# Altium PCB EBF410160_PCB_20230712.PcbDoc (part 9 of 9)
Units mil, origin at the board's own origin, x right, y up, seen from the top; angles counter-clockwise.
Board outline 5393.69 x 3858.26 mil, 6 copper layers (TOP, GND02, ART03, POW04, GND05, BOTTOM), stack 47.2 mil thick; 572 components, 434 nets, 2057 pads, 1177 vias.
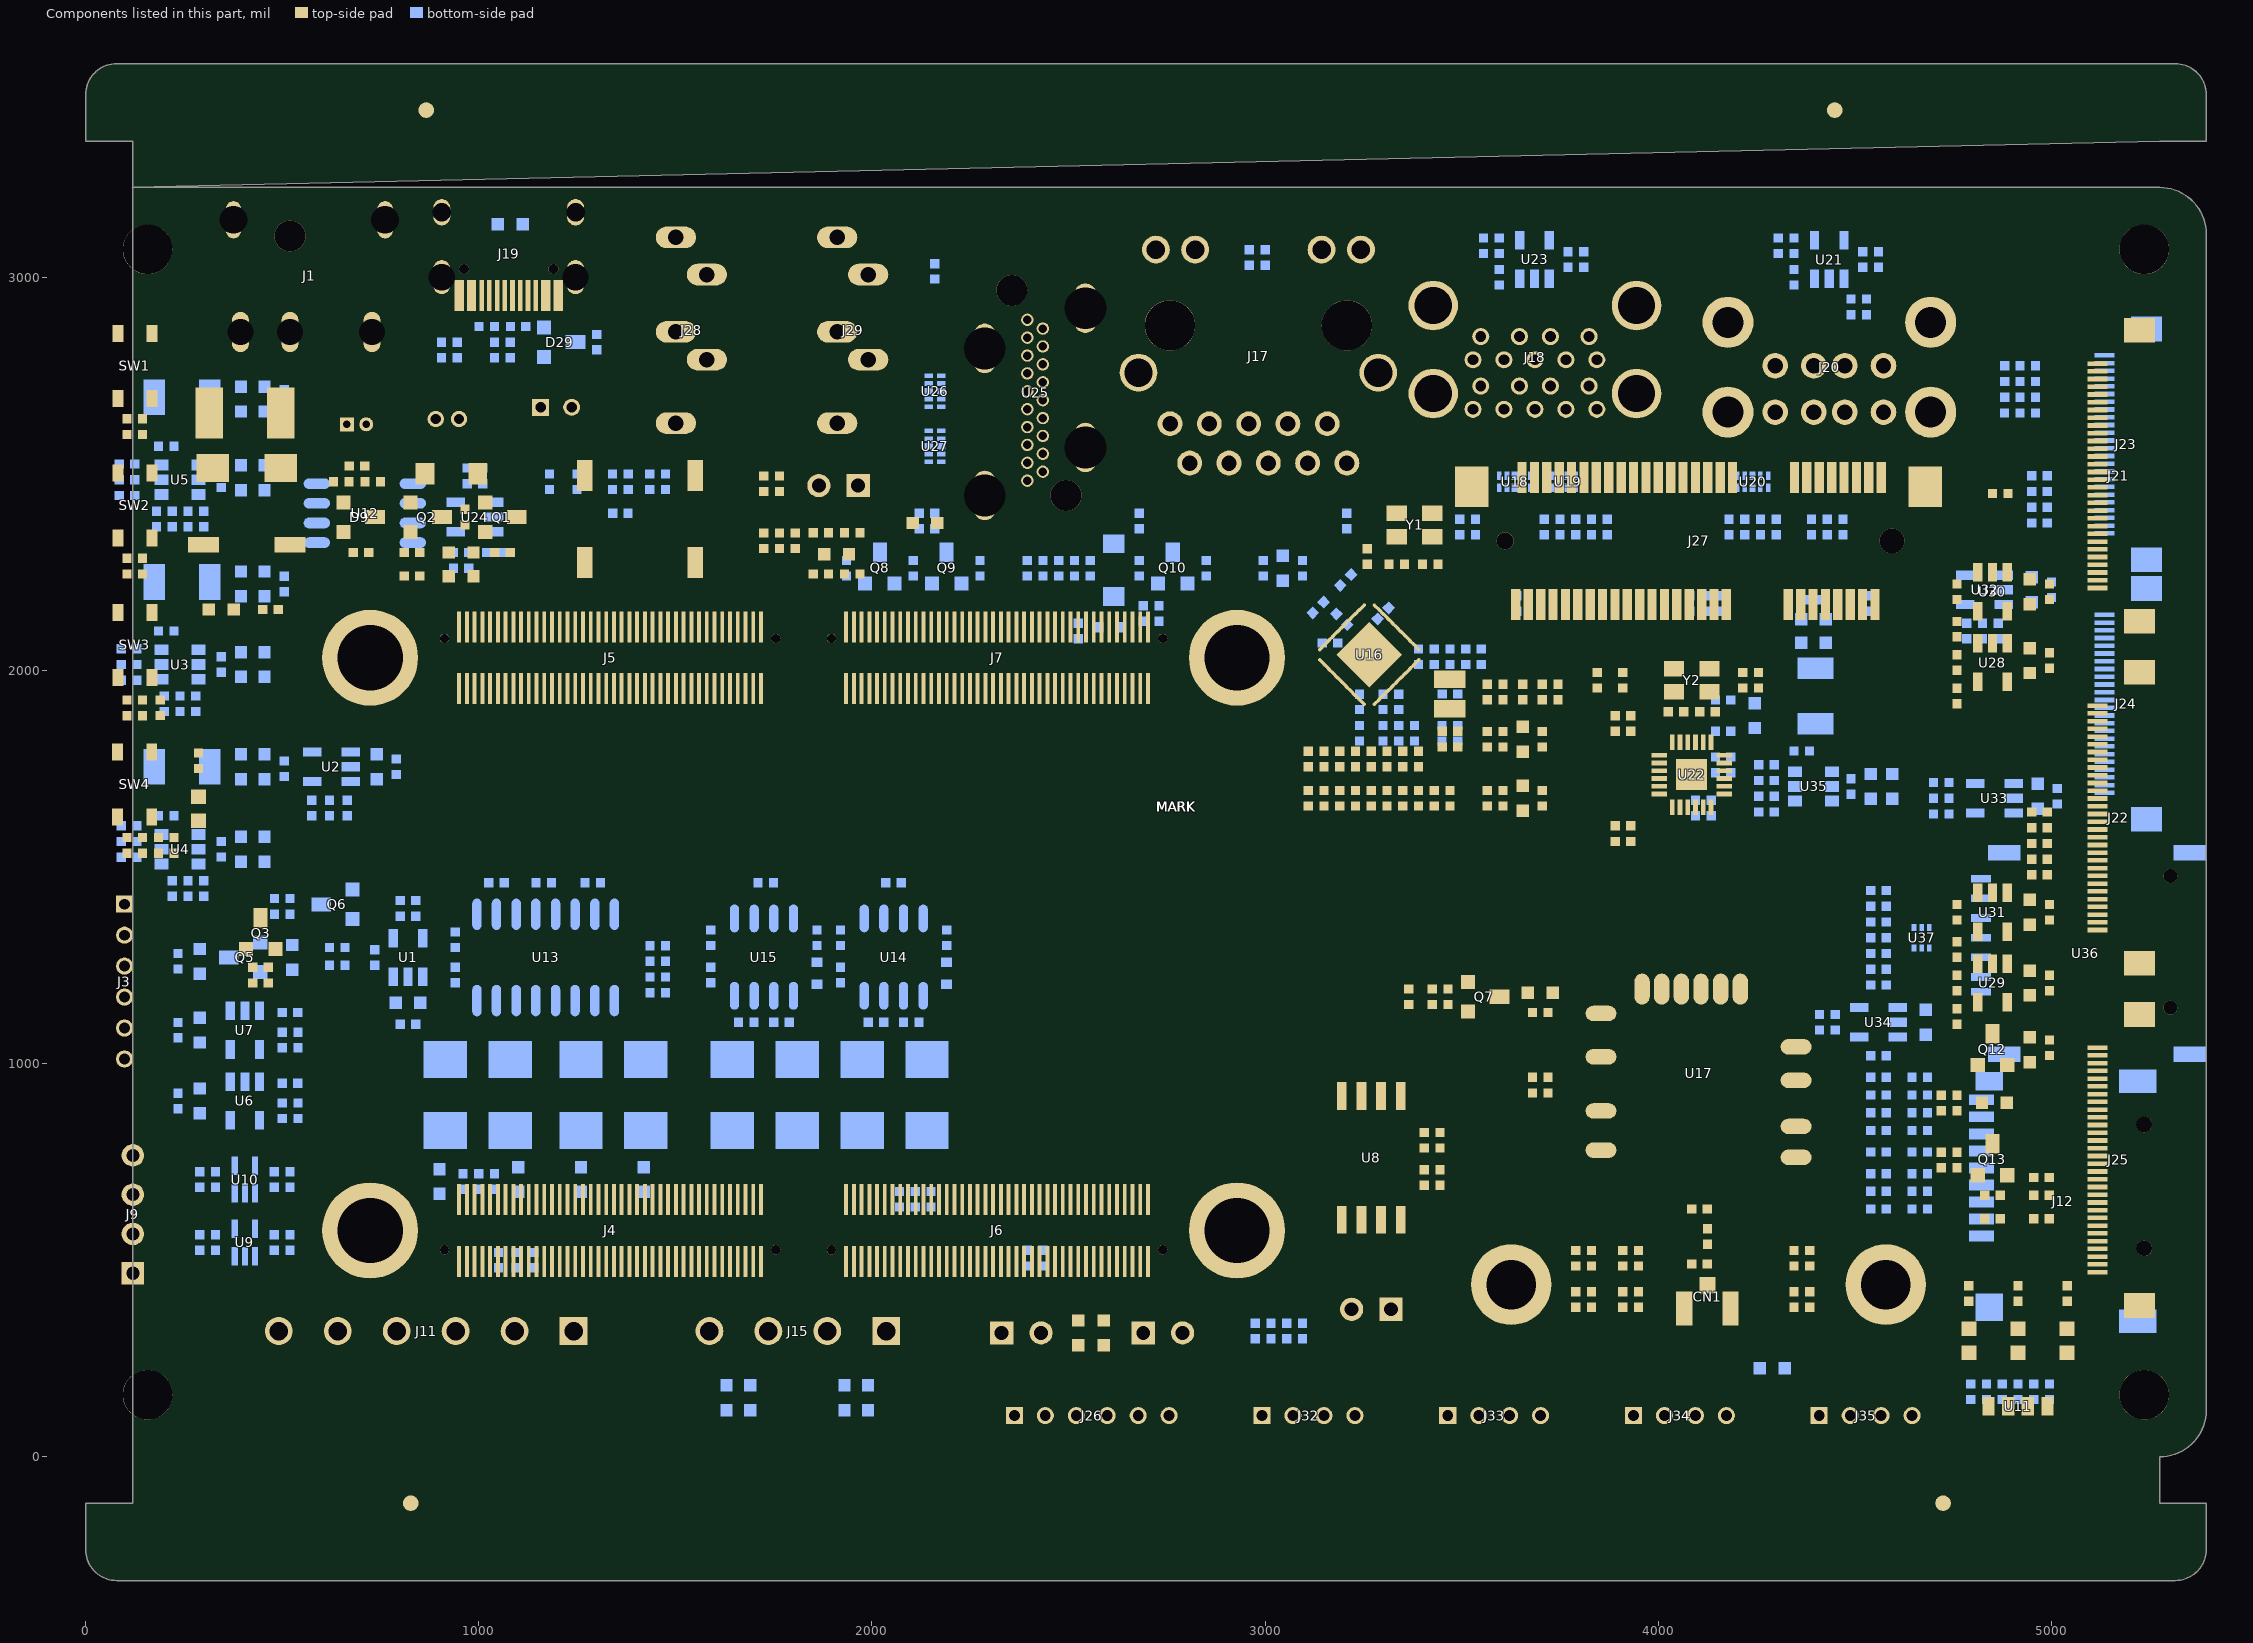
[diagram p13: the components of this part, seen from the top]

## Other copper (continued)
BOTTOM:
  region net HDMI_TX0N_PORT: 2379.42,2723.28 2379.42,2709.97 2395.6,2709.54 2395.17,2725.72 2381.86,2725.72 2381.65,2725.71 2381.44,2725.68 2381.23,2725.63 2381.03,2725.57 2380.83,2725.49 2380.64,2725.39 2380.46,2725.28 2380.29,2725.15 2380.14,2725 2379.99,2724.85 2379.86,2724.68 2379.75,2724.5 2379.65,2724.31 2379.57,2724.11 2379.51,2723.91 2379.46,2723.7 2379.43,2723.49 2379.42,2723.28
  region net HDMI_TXCLKN_PORT: 2413.99,2640.17 2423.41,2630.76 2435.15,2641.9 2423.41,2653.03 2413.99,2643.62 2413.85,2643.47 2413.72,2643.3 2413.61,2643.12 2413.51,2642.93 2413.43,2642.73 2413.36,2642.53 2413.32,2642.32 2413.29,2642.11 2413.28,2641.9 2413.29,2641.69 2413.32,2641.47 2413.36,2641.27 2413.43,2641.06 2413.51,2640.87 2413.61,2640.68 2413.72,2640.5 2413.85,2640.33 2413.99,2640.17
  region net SS_TXN: 3793.25,2792.32 3780.33,2805.24 3764.24,2790.12 3780.33,2775 3793.25,2787.92 3793.43,2788.12 3793.6,2788.33 3793.74,2788.56 3793.87,2788.8 3793.97,2789.05 3794.06,2789.31 3794.11,2789.58 3794.15,2789.85 3794.16,2790.12 3794.15,2790.39 3794.11,2790.66 3794.06,2790.93 3793.97,2791.18 3793.87,2791.44 3793.74,2791.68 3793.6,2791.91 3793.43,2792.12 3793.25,2792.32
  region net HDMI_TXDDC_SCL_PORT: 2375.08,2571.36 2384.03,2562.41 2395.94,2573.54 2384.03,2584.67 2375.08,2575.72 2374.9,2575.52 2374.73,2575.31 2374.59,2575.08 2374.46,2574.84 2374.36,2574.59 2374.28,2574.34 2374.22,2574.07 2374.19,2573.81 2374.18,2573.54 2374.19,2573.27 2374.22,2573 2374.28,2572.74 2374.36,2572.49 2374.46,2572.24 2374.59,2572 2374.73,2571.77 2374.9,2571.56 2375.08,2571.36
  region net B_DP3: 4421.94,2633.95 4421.94,2650.75 4395.18,2657.59 4402.02,2630.83 4418.82,2630.83 4419.09,2630.84 4419.36,2630.88 4419.63,2630.94 4419.89,2631.02 4420.14,2631.12 4420.38,2631.25 4420.61,2631.4 4420.82,2631.56 4421.02,2631.74 4421.21,2631.94 4421.37,2632.16 4421.52,2632.39 4421.65,2632.63 4421.75,2632.88 4421.83,2633.14 4421.89,2633.41 4421.93,2633.68 4421.94,2633.95
  region net HDMI_TX_HPD_PORT: 2397.18,2462.35 2406.3,2471.47 2395.18,2483.38 2383.99,2471.52 2392.78,2462.39 2392.98,2462.2 2393.19,2462.04 2393.41,2461.89 2393.65,2461.76 2393.89,2461.65 2394.15,2461.57 2394.41,2461.5 2394.67,2461.46 2394.94,2461.45 2395.21,2461.45 2395.48,2461.48 2395.74,2461.54 2396,2461.61 2396.25,2461.71 2396.49,2461.83 2396.72,2461.97 2396.93,2462.13 2397.14,2462.31 2397.18,2462.35
  region net SPKN_OUT: 1219.57,2647.64 1236.22,2647.64 1237.1,2670.17 1214.57,2669.29 1214.57,2652.64 1214.59,2652.2 1214.64,2651.77 1214.74,2651.34 1214.87,2650.93 1215.03,2650.52 1215.24,2650.14 1215.47,2649.77 1215.74,2649.42 1216.03,2649.1 1216.35,2648.81 1216.7,2648.54 1217.07,2648.31 1217.45,2648.1 1217.86,2647.94 1218.27,2647.81 1218.7,2647.71 1219.13,2647.66 1219.57,2647.64
  region net FSPI_D0: 3217.82,414.58 3199.12,395.88 3220,374.23 3240.88,395.88 3222.18,414.58 3221.98,414.77 3221.77,414.93 3221.54,415.07 3221.3,415.2 3221.05,415.3 3220.8,415.38 3220.53,415.44 3220.27,415.47 3220,415.49 3219.73,415.47 3219.47,415.44 3219.2,415.38 3218.95,415.3 3218.7,415.2 3218.46,415.07 3218.23,414.93 3218.02,414.77 3217.82,414.58
  region net HDMI_TXCLKP_PORT: 2413.99,2685.68 2423.41,2676.27 2435.15,2687.41 2423.41,2698.54 2413.99,2689.13 2413.85,2688.98 2413.72,2688.81 2413.61,2688.63 2413.51,2688.44 2413.43,2688.24 2413.36,2688.04 2413.32,2687.83 2413.29,2687.62 2413.28,2687.41 2413.29,2687.2 2413.32,2686.99 2413.36,2686.78 2413.43,2686.57 2413.51,2686.38 2413.61,2686.19 2413.72,2686.01 2413.85,2685.84 2413.99,2685.68
  region net DBG_RXD: 166.5,685.32 138.78,685.32 119.29,666.25 140.18,654.65 168.67,683.14 166.5,685.32
  region net VDD_3V3: 4367.33,99.75 4387.79,82.83 4411.94,104.49 4387.79,126.14 4367.33,109.23 4366.95,108.44 4366.64,107.63 4366.4,106.79 4366.24,105.93 4366.15,105.06 4366.14,104.19 4366.2,103.32 4366.34,102.46 4366.56,101.61 4366.84,100.79 4367.2,99.99 4367.33,99.75
  region net HOST1_DM: 3697.43,2846.97 3710.35,2834.05 3726.44,2849.17 3710.35,2864.29 3697.43,2851.37 3697.25,2851.17 3697.09,2850.96 3696.94,2850.73 3696.81,2850.49 3696.71,2850.24 3696.63,2849.98 3696.57,2849.71 3696.53,2849.44 3696.52,2849.17 3696.53,2848.9 3696.57,2848.63 3696.63,2848.36 3696.71,2848.1 3696.81,2847.85 3696.94,2847.61 3697.09,2847.38 3697.25,2847.17 3697.43,2846.97
  region net N17731599: 520.57,355.08 491.14,355.08 490.08,318.58 526.57,319.64 526.57,349.08 526.55,349.6 526.48,350.12 526.37,350.63 526.21,351.13 526.01,351.61 525.77,352.08 525.49,352.52 525.17,352.93 524.82,353.32 524.43,353.67 524.01,353.99 523.57,354.27 523.11,354.52 522.63,354.72 522.13,354.87 521.61,354.99 521.1,355.06 520.57,355.08
  region net USB3_HOST1_SSRXP: 3582.92,2787.92 3592.23,2778.61 3608.32,2790.12 3592.23,2801.63 3582.92,2792.32 3582.73,2792.12 3582.57,2791.91 3582.42,2791.68 3582.3,2791.44 3582.19,2791.18 3582.11,2790.93 3582.05,2790.66 3582.02,2790.39 3582,2790.12 3582.02,2789.85 3582.05,2789.58 3582.11,2789.31 3582.19,2789.05 3582.3,2788.8 3582.42,2788.56 3582.57,2788.33 3582.73,2788.12 3582.92,2787.92
  region net N18353176: 3115.83,3035.01 3143.76,3035.01 3145.09,3071.77 3108.33,3070.44 3108.33,3042.51 3108.36,3041.85 3108.44,3041.2 3108.58,3040.57 3108.78,3039.94 3109.03,3039.34 3109.33,3038.76 3109.68,3038.21 3110.08,3037.69 3110.52,3037.2 3111.01,3036.76 3111.53,3036.36 3112.08,3036.01 3112.66,3035.71 3113.26,3035.46 3113.89,3035.26 3114.52,3035.12 3115.17,3035.04 3115.83,3035.01
  region net N17731627: 1306.38,323.24 1276.57,353.13 1239.64,319.64 1276.57,286.16 1306.38,316.06 1306.68,316.49 1306.93,316.94 1307.15,317.42 1307.32,317.92 1307.45,318.42 1307.53,318.94 1307.57,319.46 1307.56,319.99 1307.51,320.51 1307.41,321.02 1307.27,321.52 1307.09,322.01 1306.86,322.49 1306.59,322.94 1306.38,323.24
  region net SS_TXP: 3817.92,2787.92 3828.45,2777.39 3844.54,2790.12 3828.45,2802.85 3817.92,2792.32 3817.73,2792.12 3817.57,2791.91 3817.42,2791.68 3817.3,2791.44 3817.19,2791.18 3817.11,2790.93 3817.05,2790.66 3817.02,2790.39 3817,2790.12 3817.02,2789.85 3817.05,2789.58 3817.11,2789.31 3817.19,2789.05 3817.3,2788.8 3817.42,2788.56 3817.57,2788.33 3817.73,2788.12 3817.92,2787.92
  region net HDMI_TX1N_PORT: 2413.99,2776.7 2423.41,2767.29 2435.15,2778.43 2423.41,2789.56 2413.99,2780.15 2413.85,2780 2413.72,2779.83 2413.61,2779.65 2413.51,2779.46 2413.43,2779.26 2413.36,2779.06 2413.32,2778.85 2413.29,2778.64 2413.28,2778.43 2413.29,2778.22 2413.32,2778.01 2413.36,2777.8 2413.43,2777.59 2413.51,2777.4 2413.61,2777.21 2413.72,2777.03 2413.85,2776.86 2413.99,2776.7
  region net B_DM2: 4443.44,2752.89 4452.22,2752.89 4475.1,2775.6 4451.49,2765.34 4441.24,2755.1 4443.44,2752.89
  region net N17697466: 2857.53,3042.51 2857.53,3070.44 2820.77,3071.77 2822.1,3035.01 2850.03,3035.01 2850.68,3035.04 2851.33,3035.12 2851.97,3035.26 2852.6,3035.46 2853.2,3035.71 2853.78,3036.01 2854.33,3036.36 2854.85,3036.76 2855.33,3037.2 2855.78,3037.69 2856.17,3038.21 2856.53,3038.76 2856.83,3039.34 2857.08,3039.94 2857.28,3040.57 2857.42,3041.2 2857.5,3041.85 2857.53,3042.51
  region net EDP_TP_INT: 2459.51,126.14 2440.94,126.14 2440.4,103.94 2462.59,104.49 2462.59,123.06 2462.58,123.33 2462.55,123.6 2462.49,123.86 2462.41,124.12 2462.31,124.36 2462.18,124.6 2462.04,124.83 2461.87,125.04 2461.69,125.24 2461.49,125.42 2461.28,125.58 2461.05,125.73 2460.82,125.85 2460.57,125.96 2460.31,126.04 2460.05,126.1 2459.78,126.13 2459.51,126.14
  region net B_DP2: 4426.1,2747.89 4426.1,2773.02 4395.18,2775.7 4397.86,2744.78 4422.98,2744.78 4423.26,2744.79 4423.53,2744.83 4423.79,2744.89 4424.05,2744.97 4424.3,2745.07 4424.54,2745.2 4424.77,2745.34 4424.99,2745.51 4425.19,2745.69 4425.37,2745.89 4425.54,2746.11 4425.68,2746.34 4425.81,2746.58 4425.91,2746.83 4425.99,2747.09 4426.05,2747.35 4426.09,2747.62 4426.1,2747.89
  region net N17702199: 1632.99,323.18 1611.47,344.7 1585.16,319.64 1611.47,294.59 1632.99,316.11 1633.28,316.43 1633.55,316.78 1633.78,317.14 1633.98,317.53 1634.15,317.93 1634.28,318.35 1634.38,318.78 1634.43,319.21 1634.45,319.64 1634.43,320.08 1634.38,320.51 1634.28,320.94 1634.15,321.36 1633.98,321.76 1633.78,322.15 1633.55,322.51 1633.28,322.86 1632.99,323.18
  region net N18585387: 3049.21,123.06 3049.21,104.49 3071.4,103.94 3070.86,126.14 3052.29,126.14 3052.02,126.13 3051.75,126.1 3051.49,126.04 3051.23,125.96 3050.98,125.85 3050.75,125.73 3050.52,125.58 3050.31,125.42 3050.11,125.24 3049.93,125.04 3049.76,124.83 3049.62,124.6 3049.49,124.36 3049.39,124.12 3049.31,123.86 3049.25,123.6 3049.22,123.33 3049.21,123.06
  region net B_DM3: 4433.05,2624.94 4474.07,2624.94 4475.11,2657.49 4442.38,2658.09 4430.18,2629.27 4430.09,2629.01 4430.02,2628.75 4429.97,2628.48 4429.94,2628.21 4429.94,2627.94 4429.96,2627.67 4430.01,2627.4 4430.07,2627.14 4430.17,2626.88 4430.28,2626.63 4430.41,2626.4 4430.57,2626.17 4430.74,2625.97 4430.93,2625.77 4431.14,2625.6 4431.36,2625.44 4431.59,2625.3 4431.84,2625.18 4432.09,2625.09 4432.35,2625.02 4432.62,2624.97 4432.89,2624.94 4433.05,2624.94
  pour cut-out: 519,932 444,932 444,969 519,969 519,932
  region net DBG_TXD: 158.19,568.72 140.18,586.72 119.23,566.54 140.18,546.36 158.19,564.36 158.37,564.56 158.53,564.77 158.68,565 158.8,565.24 158.91,565.49 158.99,565.74 159.04,566.01 159.08,566.27 159.09,566.54 159.08,566.81 159.04,567.08 158.99,567.34 158.91,567.59 158.8,567.84 158.68,568.08 158.53,568.31 158.37,568.52 158.19,568.72
  region net 3V3_OUT: 120.39,1078.67 120.39,1090.32 96.97,1092.09 98.74,1068.67 110.39,1068.67 111.27,1068.7 112.13,1068.82 112.98,1069.01 113.81,1069.27 114.62,1069.6 115.39,1070.01 116.13,1070.47 116.82,1071.01 117.47,1071.59 118.05,1072.24 118.59,1072.93 119.05,1073.67 119.46,1074.44 119.79,1075.25 120.05,1076.08 120.24,1076.93 120.36,1077.79 120.39,1078.67
  region net 3V3_EDP: 2320.09,99.75 2340.55,82.83 2364.7,104.49 2340.55,126.14 2320.09,109.23 2319.71,108.44 2319.4,107.63 2319.16,106.79 2319,105.93 2318.91,105.06 2318.9,104.19 2318.96,103.32 2319.1,102.46 2319.32,101.61 2319.6,100.79 2319.96,99.99 2320.09,99.75
  region net N18585389: 3127.95,123.06 3127.95,104.49 3150.14,103.94 3149.6,126.14 3131.03,126.14 3130.76,126.13 3130.49,126.1 3130.23,126.04 3129.97,125.96 3129.72,125.85 3129.49,125.73 3129.26,125.58 3129.05,125.42 3128.85,125.24 3128.67,125.04 3128.5,124.83 3128.36,124.6 3128.23,124.36 3128.13,124.12 3128.05,123.86 3127.99,123.6 3127.96,123.33 3127.95,123.06
  region net HDMI_TX0P_PORT: 2381.86,2739.69 2395.17,2739.69 2395.6,2755.87 2379.42,2755.44 2379.42,2742.13 2379.43,2741.92 2379.46,2741.71 2379.51,2741.5 2379.57,2741.29 2379.65,2741.1 2379.75,2740.91 2379.86,2740.73 2379.99,2740.56 2380.14,2740.4 2380.29,2740.26 2380.46,2740.13 2380.64,2740.02 2380.83,2739.92 2381.03,2739.84 2381.23,2739.77 2381.44,2739.73 2381.65,2739.7 2381.86,2739.69
  region net N18355550: 970.57,355.08 941.14,355.08 940.08,318.58 976.57,319.64 976.57,349.08 976.55,349.6 976.48,350.12 976.37,350.63 976.21,351.13 976.01,351.61 975.77,352.08 975.49,352.52 975.17,352.93 974.82,353.32 974.43,353.67 974.01,353.99 973.57,354.27 973.11,354.52 972.63,354.72 972.13,354.87 971.61,354.99 971.1,355.06 970.57,355.08
  region net EDP_TP_RESET: 2535,122.89 2522.93,122.89 2519.14,103.94 2538.08,107.74 2538.08,119.81 2538.07,120.08 2538.03,120.34 2537.98,120.61 2537.89,120.86 2537.79,121.11 2537.67,121.35 2537.52,121.57 2537.36,121.79 2537.18,121.99 2536.98,122.17 2536.77,122.33 2536.54,122.48 2536.3,122.6 2536.05,122.7 2535.8,122.78 2535.53,122.84 2535.27,122.88 2535,122.89
  region net 5V_OUT: 120.39,1236.15 120.39,1247.8 96.97,1249.57 98.74,1226.15 110.39,1226.15 111.27,1226.18 112.13,1226.3 112.98,1226.49 113.81,1226.75 114.62,1227.08 115.39,1227.49 116.13,1227.95 116.82,1228.49 117.47,1229.07 118.05,1229.72 118.59,1230.41 119.05,1231.15 119.46,1231.92 119.79,1232.73 120.05,1233.56 120.24,1234.41 120.36,1235.27 120.39,1236.15
  region net HDMI_TX2P_PORT: 2383.32,2877.56 2393.71,2877.56 2395.6,2892.28 2380.88,2890.39 2380.88,2880 2380.89,2879.79 2380.92,2879.58 2380.96,2879.37 2381.03,2879.17 2381.11,2878.97 2381.21,2878.78 2381.32,2878.6 2381.45,2878.43 2381.59,2878.27 2381.75,2878.13 2381.92,2878 2382.1,2877.89 2382.29,2877.79 2382.49,2877.71 2382.69,2877.64 2382.9,2877.6 2383.11,2877.57 2383.32,2877.56
  region net HDMI_TX2N_PORT: 2379.42,2859.69 2379.42,2846.38 2395.6,2845.95 2395.17,2862.13 2381.86,2862.13 2381.65,2862.12 2381.44,2862.09 2381.23,2862.04 2381.03,2861.98 2380.83,2861.9 2380.64,2861.8 2380.46,2861.68 2380.29,2861.56 2380.14,2861.41 2379.99,2861.25 2379.86,2861.09 2379.75,2860.91 2379.65,2860.72 2379.57,2860.52 2379.51,2860.32 2379.46,2860.11 2379.43,2859.9 2379.42,2859.69
  region net N17702194: 1689.48,316.46 1711.36,294.59 1737.66,319.63 1711.42,344.76 1689.54,323.59 1689.24,323.28 1688.97,322.93 1688.73,322.57 1688.52,322.19 1688.35,321.79 1688.21,321.37 1688.11,320.95 1688.05,320.52 1688.02,320.08 1688.03,319.65 1688.08,319.21 1688.17,318.79 1688.29,318.37 1688.45,317.96 1688.65,317.57 1688.88,317.2 1689.14,316.85 1689.43,316.52 1689.48,316.46
  region net HDMI_TXDDC_SDA_PORT: 2454.63,2553.05 2445.68,2562 2433.77,2550.87 2445.68,2539.74 2454.63,2548.69 2454.81,2548.89 2454.98,2549.1 2455.12,2549.33 2455.25,2549.57 2455.35,2549.82 2455.43,2550.07 2455.49,2550.34 2455.52,2550.6 2455.53,2550.87 2455.52,2551.14 2455.49,2551.4 2455.43,2551.67 2455.35,2551.92 2455.25,2552.17 2455.12,2552.41 2454.98,2552.64 2454.81,2552.85 2454.63,2553.05
  region net PHY1_LED1: 2757.53,3040.01 2757.53,3070.44 2721.21,3071.32 2722.1,3035.01 2752.53,3035.01 2752.97,3035.03 2753.4,3035.08 2753.83,3035.18 2754.24,3035.31 2754.64,3035.48 2755.03,3035.68 2755.4,3035.91 2755.74,3036.18 2756.07,3036.47 2756.36,3036.79 2756.63,3037.14 2756.86,3037.51 2757.06,3037.89 2757.23,3038.3 2757.36,3038.71 2757.45,3039.14 2757.51,3039.57 2757.53,3040.01
  region net HDMI_TX1P_PORT: 2413.99,2822.21 2423.41,2812.8 2435.15,2823.94 2423.41,2835.07 2413.99,2825.66 2413.85,2825.51 2413.72,2825.34 2413.61,2825.16 2413.51,2824.97 2413.43,2824.77 2413.36,2824.57 2413.32,2824.36 2413.29,2824.15 2413.28,2823.94 2413.29,2823.72 2413.32,2823.51 2413.36,2823.31 2413.43,2823.1 2413.51,2822.91 2413.61,2822.72 2413.72,2822.54 2413.85,2822.37 2413.99,2822.21
  region net HDMI_TX_CEC_PORT: 2375.08,2616.84 2384.03,2607.89 2395.94,2619.02 2384.03,2630.15 2375.08,2621.2 2374.9,2621 2374.73,2620.79 2374.59,2620.56 2374.46,2620.32 2374.36,2620.07 2374.28,2619.82 2374.22,2619.55 2374.19,2619.29 2374.18,2619.02 2374.19,2618.75 2374.22,2618.49 2374.28,2618.22 2374.36,2617.97 2374.46,2617.72 2374.59,2617.48 2374.73,2617.25 2374.9,2617.04 2375.08,2616.84
  pour cut-out: 519,1112 444,1112 444,1149 519,1149 519,1112
  region net HOST1_DP: 3673.03,2851.37 3662.23,2862.17 3646.14,2849.17 3662.23,2836.17 3673.03,2846.97 3673.22,2847.17 3673.38,2847.38 3673.53,2847.61 3673.65,2847.85 3673.76,2848.1 3673.84,2848.36 3673.9,2848.63 3673.93,2848.9 3673.95,2849.17 3673.93,2849.44 3673.9,2849.71 3673.84,2849.98 3673.76,2850.24 3673.65,2850.49 3673.53,2850.73 3673.38,2850.96 3673.22,2851.17 3673.03,2851.37
  region net N15603170: 3216.97,2491.82 3230.4,2505.25 3208.13,2530.64 3185.86,2505.25 3199.29,2491.82 3200.1,2491.08 3200.96,2490.42 3201.88,2489.83 3202.85,2489.33 3203.85,2488.91 3204.89,2488.58 3205.96,2488.34 3207.04,2488.2 3208.13,2488.16 3209.22,2488.2 3210.3,2488.34 3211.37,2488.58 3212.41,2488.91 3213.41,2489.33 3214.38,2489.83 3215.3,2490.42 3216.16,2491.08 3216.97,2491.82
  region net PHY1_LED2: 3279.19,3040.01 3279.19,3070.44 3242.88,3071.32 3243.76,3035.01 3274.19,3035.01 3274.63,3035.03 3275.06,3035.08 3275.49,3035.18 3275.9,3035.31 3276.31,3035.48 3276.69,3035.68 3277.06,3035.91 3277.41,3036.18 3277.73,3036.47 3278.02,3036.79 3278.29,3037.14 3278.52,3037.51 3278.72,3037.89 3278.89,3038.3 3279.02,3038.71 3279.12,3039.14 3279.17,3039.57 3279.19,3040.01
  region net N17702222: 1932.99,323.18 1911.47,344.7 1885.16,319.64 1911.47,294.59 1932.99,316.11 1933.28,316.43 1933.55,316.78 1933.78,317.14 1933.98,317.53 1934.15,317.93 1934.28,318.35 1934.38,318.78 1934.43,319.21 1934.45,319.64 1934.43,320.08 1934.38,320.51 1934.28,320.94 1934.15,321.36 1933.98,321.76 1933.78,322.15 1933.55,322.51 1933.28,322.86 1932.99,323.18
  pour cut-out: 1626,77 1609,77 1609,98 1608,98 1608,199 1713,199 1713,98 1626,98 1626,77
  pour cut-out: 2011,106 1909,106 1909,186 2011,186 2011,106
  pour cut-out: 2531,235 2494,235 2494,395 2531,395 2531,235
  pour cut-out: 246 vertices and 0 holes, not listed, extent 65,256 5350,3185
  pour cut-out: 2020,274 1906,274 1906,322 1909,322 1909,326 1885,326 1885,365 2040,365 2040,326 2029,326 2029,303 2020,303 2020,274
  pour cut-out: 1740,275 1592,275 1592,326 1584,326 1584,365 1746,365 1746,326 1740,326 1740,275
  pour cut-out: 3088,283 2986,283 2986,319 3088,319 3088,283
  pour cut-out: 2481,439 2447,439 2447,445 2441,445 2441,480 2377,480 2377,514 2441,514 2441,534 2501,534 2501,445 2481,445 2481,439
  pour cut-out: 2165,520 2147,520 2147,549 2165,549 2165,520
  pour cut-out: 2155,657 2081,657 2081,693 2155,693 2155,657
  pour cut-out: 2092,824 2034,824 2034,892 2092,892 2092,824
  pour cut-out: 1750,833 1703,833 1703,895 1750,895 1750,833
  pour cut-out: 1325,1540 1290,1540 1290,1556 1270,1556 1270,1598 1277,1598 1291,1584 1291,1572 1303,1572 1325,1550 1325,1540
  pour cut-out: 1358.35,2405.38 1322.59,2405.38 1322.59,2454.16 1358.35,2454.16 1358.35,2405.38
  pour cut-out: 1463.93,2481.89 1342.98,2481.89 1342.98,2517.64 1463.93,2517.64 1463.93,2481.89
  pour cut-out: 1181.93,2785.94 1142.84,2785.94 1142.84,2865.8 1181.93,2865.8 1181.93,2785.94
  pour cut-out: 1297.54,2811 1183.27,2811 1183.27,2859.11 1297.54,2859.11 1297.54,2811
  pour cut-out: 1167.56,2870.47 1142.17,2870.47 1142.17,2925.94 1167.56,2925.94 1167.56,2870.47
  region net USB3_HOST1_SSRXN: 3557.03,2792.32 3544.11,2805.24 3528.02,2790.12 3544.11,2775 3557.03,2787.92 3557.21,2788.12 3557.38,2788.33 3557.52,2788.56 3557.65,2788.8 3557.75,2789.05 3557.84,2789.31 3557.89,2789.58 3557.93,2789.85 3557.94,2790.12 3557.93,2790.39 3557.89,2790.66 3557.84,2790.93 3557.75,2791.18 3557.65,2791.44 3557.52,2791.68 3557.38,2791.91 3557.21,2792.12 3557.03,2792.32
  region net N17702231: 1972.06,316.57 2000.98,287.59 2037.66,319.64 2000.98,351.7 1972.06,322.72 1971.8,322.36 1971.58,321.99 1971.4,321.59 1971.24,321.18 1971.13,320.76 1971.05,320.34 1971.01,319.9 1971,319.46 1971.04,319.03 1971.11,318.6 1971.22,318.18 1971.37,317.77 1971.55,317.37 1971.76,316.99 1972.01,316.63 1972.06,316.57
  region net N17731608: 820.57,355.08 791.14,355.08 790.08,318.58 826.57,319.64 826.57,349.08 826.55,349.6 826.48,350.12 826.37,350.63 826.21,351.13 826.01,351.61 825.77,352.08 825.49,352.52 825.17,352.93 824.82,353.32 824.43,353.67 824.01,353.99 823.57,354.27 823.11,354.52 822.63,354.72 822.13,354.87 821.61,354.99 821.1,355.06 820.57,355.08

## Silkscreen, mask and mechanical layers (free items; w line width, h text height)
OUTLINE:
  lines w1: 118.11,0 5275.58,0 ; 118.11,3228.34 5275.58,3228.34 ; 120,0 120,-118.11 0,-118.11 0,-236.22 ccw(c78.74,-236.22) 78.74,-314.96 5314.95,-314.96 ccw(c5314.95,-236.22) 5393.69,-236.22 5393.69,-118.11 5275.58,-118.11 5275.58,0 ; 120,3228.34 120,3346.45 0,3346.45 0,3464.56 cw(c78.74,3464.56) 78.74,3543.3 5314.95,3543.3 cw(c5314.95,3464.56) 5393.69,3464.56 5393.69,3346.45 5275.58,3346.45 5275.58,3228.34 ; 5275.58,0 ccw(c5275.58,118.11) 5393.69,118.11 5393.69,3110.23 ccw(c5275.58,3110.23) 5275.58,3228.34
NCLEGEND-1-6:
  circle w1: c7131.5,3710 r19.68
  lines w1: 6682,-1915 11518,-1915 ; 6682,-1665 11518,-1665 ; 6682,-1415 11518,-1415 ; 6682,-1165 11518,-1165 ; 6682,-915 11518,-915 ; 6682,-665 11518,-665 ; 6682,-415 11518,-415 ; 6682,-165 11518,-165 ; 6682,85 11518,85 ; 6682,335 11518,335 ; 6682,585 11518,585 ; 6682,835 11518,835 ; 6682,1085 11518,1085 ; 6682,1335 11518,1335 ; 6682,1585 11518,1585 ; 6682,1835 11518,1835 ; 6682,2085 11518,2085 ; 6682,2335 11518,2335 ; 6682,2585 11518,2585 ; 6682,2835 11518,2835 ; 6682,3085 11518,3085 ; 6682,3335 11518,3335 ; 6682,3585 11518,3585 ; 6682,3835 11518,3835 ; 6682,4085 11518,4085 ; 6682,4335 11518,4335 ; 6682,4585 11518,4585 ; 6682,4835 11518,4835 ; 6682,5085 11518,5085 ; 6682,5335 11518,5335 ; 6682,5585 11518,5585 ; 6682,5835 11518,5835 ; 6682,6085 11518,6085 ; 6682,6335 11518,6335 ; 7125.5,5710 7137.5,5710 ; 7131.5,5704 7131.5,5716 ; 7581,-2165 7581,6085 ; 9472,-2165 9472,6085 ; 10743,-2165 10743,6085 ; 6682,-2165 6682,6585 11518,6585 11518,-2165 6682,-2165 ; 7096.06,-2075.43 ccw(c7096.06,-2040) 7096.06,-2004.57 7166.94,-2004.57 ccw(c7166.94,-2040) 7166.94,-2075.43 7096.06,-2075.43 ; 7101.67,4710 7110.41,4688.91 7131.5,4680.17 7152.59,4688.91 7161.33,4710 7152.59,4731.09 7131.5,4739.83 7110.41,4731.09 7101.67,4710 ; 7103.9,-1305.7 ccw(c7103.9,-1290) 7103.9,-1274.3 7159.1,-1274.3 ccw(c7159.1,-1290) 7159.1,-1305.7 7103.9,-1305.7 ; 7107.9,-809.7 ccw(c7107.9,-790) 7107.9,-770.3 7155.1,-770.3 ccw(c7155.1,-790) 7155.1,-809.7 7107.9,-809.7 ; 7109.85,-1063.62 ccw(c7109.85,-1040) 7109.85,-1016.38 7153.15,-1016.38 ccw(c7153.15,-1040) 7153.15,-1063.62 7109.85,-1063.62 ; 7111.81,-1579.37 ccw(c7111.81,-1540) 7111.81,-1500.63 7151.19,-1500.63 ccw(c7151.19,-1540) 7151.19,-1579.37 7111.81,-1579.37 ; 7111.81,3445.24 7111.81,3474.76 7151.19,3474.76 7151.19,3445.24 7111.81,3445.24 ; 7114.77,4193.27 7131.5,4226.73 7148.23,4193.27 7114.77,4193.27 ; 7117.72,4460 7131.5,4473.78 7145.28,4460 7131.5,4446.22 7117.72,4460 ; 7118.7,4953.6 7131.5,4947.2 7144.3,4953.6 7144.3,4966.4 7131.5,4972.8 7118.7,4966.4 7118.7,4953.6 ; 7119.69,-563.62 ccw(c7119.69,-540) 7119.69,-516.38 7143.31,-516.38 ccw(c7143.31,-540) 7143.31,-563.62 7119.69,-563.62 ; 7120.67,5210 7126.09,5199.17 7136.91,5199.17 7142.33,5210 7136.91,5220.83 7126.09,5220.83 7120.67,5210 ; 7121.66,5450.16 7141.34,5450.16 7141.34,5469.84 7121.66,5469.84 7121.66,5450.16 ; 7127.07,3933.43 ccw(c7127.07,3960) 7127.07,3986.57 7135.93,3986.57 ccw(c7135.93,3960) 7135.93,3933.43 7127.07,3933.43 ; 7131.5,-1884.49 cw(c7131.5,-1790) 7131.5,-1695.51 cw(c7131.5,-1790) 7131.5,-1884.49
  text "DRILL CHART: TOP to BOTTOM" at 7800,6397.5 h125
  text "ALL UNITS ARE IN MILS" at 8050,6147.5 h125
  text "FIGURE" at 6831.5,5897.5 h125
  text "SIZE" at 8326.5,5897.5 h125
  text "PLATED" at 9807.5,5897.5 h125
  text "QTY" at 10980.5,5897.5 h125
  text "12.0" at 8326.5,5647.5 h125
  text "PLATED" at 9807.5,5647.5 h125
  text "1177" at 10930.5,5647.5 h125
  text "19.685" at 8226.5,5397.5 h125
  text "PLATED" at 9807.5,5397.5 h125
  text "2" at 11080.5,5397.5 h125
  text "21.654" at 8226.5,5147.5 h125
  text "PLATED" at 9807.5,5147.5 h125
  text "19" at 11030.5,5147.5 h125
  text "25.591" at 8226.5,4897.5 h125
  text "PLATED" at 9807.5,4897.5 h125
  text "2" at 11080.5,4897.5 h125
  text "27.559" at 8226.5,4647.5 h125
  text "PLATED" at 9807.5,4647.5 h125
  text "30" at 11030.5,4647.5 h125
  text "27.559" at 8226.5,4397.5 h125
  text "PLATED" at 9807.5,4397.5 h125
  text "18" at 11030.5,4397.5 h125
  text "33.465" at 8226.5,4147.5 h125
  text "PLATED" at 9807.5,4147.5 h125
  text "4" at 11080.5,4147.5 h125
  text "35.43" at 8276.5,3897.5 h125
  text "PLATED" at 9807.5,3897.5 h125
  text "8" at 11080.5,3897.5 h125
  text "39.37" at 8276.5,3647.5 h125
  text "PLATED" at 9807.5,3647.5 h125
  text "8" at 11080.5,3647.5 h125
  text "39.37" at 8276.5,3397.5 h125
  text "PLATED" at 9807.5,3397.5 h125
  text "10" at 11030.5,3397.5 h125
  text "47.244" at 8226.5,3147.5 h125
  text "PLATED" at 9807.5,3147.5 h125
  text "14" at 11030.5,3147.5 h125
  text "72.047" at 8226.5,2897.5 h125
  text "PLATED" at 9807.5,2897.5 h125
  text "2" at 11080.5,2897.5 h125
  text "78.74" at 8276.5,2647.5 h125
  text "PLATED" at 9807.5,2647.5 h125
  text "4" at 11080.5,2647.5 h125
  text "125.98" at 8226.5,2397.5 h125
  text "PLATED" at 9807.5,2397.5 h125
  text "2" at 11080.5,2397.5 h125
  text "166.142" at 8176.5,2147.5 h125
  text "PLATED" at 9807.5,2147.5 h125
  text "4" at 11080.5,2147.5 h125
  text "23.622" at 8226.5,1897.5 h125
  text "NON-PLATED" at 9607.5,1897.5 h125
  text "8" at 11080.5,1897.5 h125
  text "25.59" at 8276.5,1647.5 h125
  text "NON-PLATED" at 9607.5,1647.5 h125
  text "2" at 11080.5,1647.5 h125
  text "35.433" at 8226.5,1397.5 h125
  text "NON-PLATED" at 9607.5,1397.5 h125
  text "2" at 11080.5,1397.5 h125
  text "40.0" at 8326.5,1147.5 h125
  text "NON-PLATED" at 9607.5,1147.5 h125
  text "2" at 11080.5,1147.5 h125
  text "43.307" at 8226.5,897.5 h125
  text "NON-PLATED" at 9607.5,897.5 h125
  text "1" at 11080.5,897.5 h125
  text "62.992" at 8226.5,647.5 h125
  text "NON-PLATED" at 9607.5,647.5 h125
  text "1" at 11080.5,647.5 h125
  text "78.701" at 8226.5,397.5 h125
  text "NON-PLATED" at 9607.5,397.5 h125
  text "1" at 11080.5,397.5 h125
  text "78.74" at 8276.5,147.5 h125
  text "NON-PLATED" at 9607.5,147.5 h125
  text "2" at 11080.5,147.5 h125
  text "125.984" at 8176.5,-102.5 h125
  text "NON-PLATED" at 9607.5,-102.5 h125
  text "4" at 11080.5,-102.5 h125
  text "127.953" at 8176.5,-352.5 h125
  text "NON-PLATED" at 9607.5,-352.5 h125
  text "2" at 11080.5,-352.5 h125
  text "47.24x23.62" at 7976.5,-602.5 h125
  text "PLATED" at 9807.5,-602.5 h125
  text "2" at 11080.5,-602.5 h125
  text "66.902x19.701" at 7876.5,-852.5 h125
  text "PLATED" at 9807.5,-852.5 h125
  text "3" at 11080.5,-852.5 h125
  text "66.93x23.62" at 7976.5,-1102.5 h125
  text "PLATED" at 9807.5,-1102.5 h125
  text "2" at 11080.5,-1102.5 h125
  text "70.902x15.701" at 7876.5,-1352.5 h125
  text "PLATED" at 9807.5,-1352.5 h125
  text "2" at 11080.5,-1352.5 h125
  text "78.74x39.37" at 7976.5,-1602.5 h125
  text "PLATED" at 9807.5,-1602.5 h125
  text "10" at 11030.5,-1602.5 h125
  text "94.488x94.488" at 7876.5,-1852.5 h125
  text "PLATED" at 9807.5,-1852.5 h125
  text "4" at 11080.5,-1852.5 h125
  text "106.299x35.429" at 7826.5,-2102.5 h125
  text "PLATED" at 9807.5,-2102.5 h125
  text "4" at 11080.5,-2102.5 h125
DRAWING_ORIGIN:
  lines w1: -25,0 25,0 ; 0,-25 0,25
Mechanical 255:
  lines w1: 935,440 1745,440 1745,710 935,710 935,440 ; 935,1815 1750,1815 1750,2200 935,2200 935,1815 ; 1910,1885 2755,1885 2755,2170 1910,2170 1910,1885 ; 1925,435 2715,435 2715,720 1925,720 1925,435 ; 2105,2525 2210,2525 2210,2620 2105,2620 2105,2525 ; 2105,2650 2210,2650 2210,2765 2105,2765 2105,2650 ; 2370,2600 2415,2600 2415,2855 2370,2855 2370,2600 ; 3090,1890 3090,2075 3210,2195 3290,2195 3420,2065 3420,1870 3385,1835 3145,1835 3090,1890 ; 3585,2435 3825,2435 3825,2555 3585,2555 3585,2435 ; 4180,2430 4310,2430 4310,2535 4180,2535 4180,2430 ; 5065,2200 5155,2200 5155,2805 5065,2805 5065,2200 ; 5075,1320 5160,1320 5160,1955 5075,1955 5075,1320 ; 5080,465 5150,465 5150,950 5080,950 5080,465 ; 5089,2330 5166,2330 5166,2807 5089,2807 5089,2330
